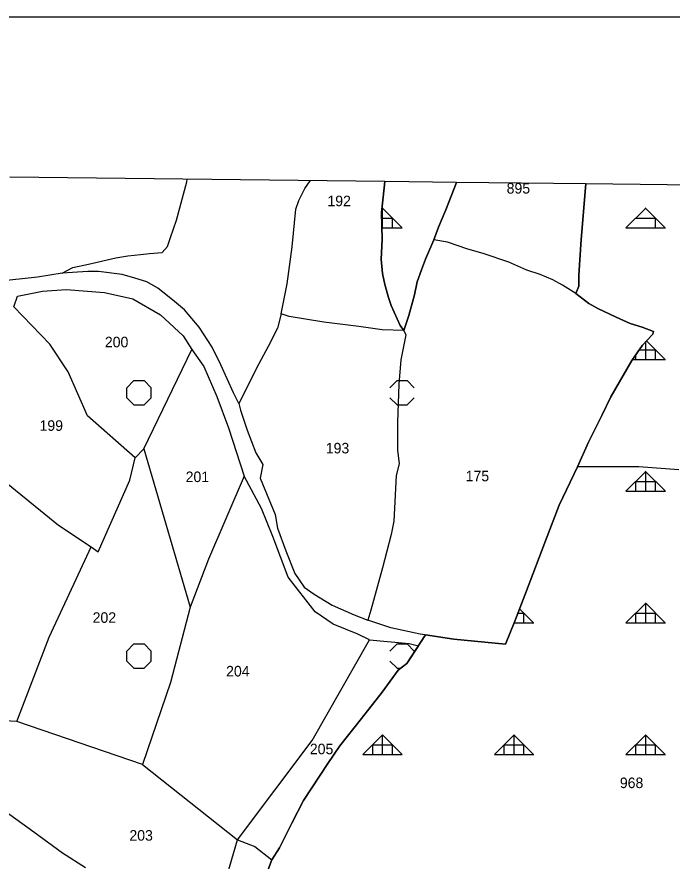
# Model space of a CAD drawing. Extents: x 410727 to 412947, y 4463506 to 4466382.
# Drawn here: x 411696.5 to 411945.5, y 4466061 to 4466381.6 of the extents above; entities that cross this region are included whole.
import ezdxf

# ---------------------------------------------------------------- set-up
doc = ezdxf.new("R2010")
doc.units = 0
for name, color, linetype in [('ADAKENARI', 7, 'Continuous'), ('KDS_PARSEL_NO', 7, 'Continuous'), ('KDS_PL', 7, 'Continuous'), ('LJ_ÇERÇEVE', 7, 'Continuous'), ('PL_AYA_ORMAN', 7, 'Continuous'), ('PL_KA_TARIM_DIGER', 7, 'Continuous'), ('TR_ORMAN', 7, 'Continuous'), ('TR_TARIMALANI', 7, 'Continuous')]:
    doc.layers.add(name, color=color, linetype=linetype)

msp = doc.modelspace()

# ---------------------------------------------------------------- linework, layer by layer
at = {"layer": 'ADAKENARI'}
for p, q in [((411836.11, 4466316.74), (411836.34, 4466319.05)), ((411863.58, 4466318.73), (411859.48, 4466308.27)), ((411910.98, 4466297.07), (411912.75, 4466318.15)), ((411835.02, 4466307.3), (411836.11, 4466316.74)), ((411859.48, 4466308.27), (411856.77, 4466301.73)), ((411835.27, 4466297.12), (411835.02, 4466307.3)), ((411856.77, 4466301.73), (411854.89, 4466297)), ((411834.96, 4466289.56), (411835.27, 4466297.12)), ((411854.89, 4466297), (411851.77, 4466289.54)), ((411910.01, 4466283.5), (411910.98, 4466297.07)), ((411835.45, 4466284.11), (411834.96, 4466289.56)), ((411851.77, 4466289.54), (411850.24, 4466285.57)), ((411850.24, 4466285.57), (411848.64, 4466280.97)), ((411836.29, 4466279.99), (411835.45, 4466284.11)), ((411910.08, 4466279.32), (411910.01, 4466283.5)), ((411837.69, 4466275.03), (411836.29, 4466279.99)), ((411848.64, 4466280.97), (411847.53, 4466276.1)), ((411908.89, 4466276.54), (411910.08, 4466279.32)), ((411847.53, 4466276.1), (411845.41, 4466268.2)), ((411913.91, 4466272.73), (411908.89, 4466276.54)), ((411838.72, 4466272), (411837.69, 4466275.03)), ((411917.32, 4466270.92), (411913.91, 4466272.73)), ((411842.17, 4466264.37), (411838.72, 4466272)), ((411924.21, 4466267.58), (411917.32, 4466270.92)), ((411845.41, 4466268.2), (411843.56, 4466262.55)), ((411929.5, 4466265.21), (411924.21, 4466267.58)), ((411843.56, 4466262.55), (411842.17, 4466264.37)), ((411934.17, 4466263.81), (411929.5, 4466265.21)), ((411938.41, 4466262.07), (411934.17, 4466263.81)), ((411934.24, 4466256.99), (411938.14, 4466261.1)), ((411938.14, 4466261.1), (411938.41, 4466262.07)), ((411930.2, 4466251.07), (411934.24, 4466256.99)), ((411922.23, 4466237.35), (411930.2, 4466251.07)), ((411918.81, 4466230.25), (411922.23, 4466237.35)), ((411918.81, 4466230.25), (411922.23, 4466237.35)), ((411913.66, 4466220.15), (411918.81, 4466230.25)), ((411909.55, 4466210.75), (411913.66, 4466220.15)), ((411902.58, 4466196.22), (411909.55, 4466210.75)), ((411897.34, 4466182.66), (411902.58, 4466196.22)), ((411890.21, 4466163.7), (411897.34, 4466182.66)), ((411885.69, 4466152.18), (411890.21, 4466163.7)), ((411882.2, 4466143.43), (411885.69, 4466152.18)), ((411844.66, 4466136.05), (411851.83, 4466146.91)), ((411851.83, 4466146.91), (411862.55, 4466145.33)), ((411862.55, 4466145.33), (411882.2, 4466143.43)), ((411841.32, 4466133.5), (411844.66, 4466136.05)), ((411835.34, 4466125.15), (411841.32, 4466133.5)), ((411827.4, 4466115.22), (411835.34, 4466125.15)), ((411819.16, 4466104.81), (411827.4, 4466115.22)), ((411814.65, 4466098.13), (411819.16, 4466104.81)), ((411805.34, 4466084.08), (411814.65, 4466098.13)), ((411801.02, 4466075.44), (411805.34, 4466084.08)), ((411796.32, 4466066.11), (411801.02, 4466075.44)), ((411793.41, 4466061.46), (411796.32, 4466066.11)), ((411790.89, 4466054.84), (411793.41, 4466061.46))]:
    msp.add_line(p, q, dxfattribs=at)
at = {"layer": 'KDS_PL'}
for p, q in [((411757.11, 4466304.43), (411761.05, 4466318.91)), ((411761.05, 4466318.91), (411761.24, 4466319.93)), ((411805.93, 4466316.38), (411807.93, 4466319.38)), ((411836.34, 4466319.05), (411836.11, 4466316.74)), ((411859.48, 4466308.27), (411863.58, 4466318.73)), ((411912.75, 4466318.15), (411910.98, 4466297.07)), ((411803.57, 4466311.84), (411805.93, 4466316.38)), ((411836.11, 4466316.74), (411835.02, 4466307.3)), ((411802.54, 4466308.57), (411803.57, 4466311.84)), ((411801.03, 4466294.34), (411802.54, 4466308.57)), ((411856.77, 4466301.73), (411859.48, 4466308.27)), ((411754.87, 4466297.83), (411757.11, 4466304.43)), ((411835.02, 4466307.3), (411835.27, 4466297.12)), ((411854.89, 4466297), (411856.77, 4466301.73)), ((411753.66, 4466294.43), (411754.87, 4466297.83)), ((411835.27, 4466297.12), (411834.96, 4466289.56)), ((411854.89, 4466297), (411851.77, 4466289.54)), ((411860.18, 4466296.1), (411854.89, 4466297)), ((411867.9, 4466293.38), (411860.18, 4466296.1)), ((411910.98, 4466297.07), (411910.01, 4466283.5)), ((411743.42, 4466291.4), (411746.81, 4466291.71)), ((411746.81, 4466291.71), (411751.72, 4466292.07)), ((411751.72, 4466292.07), (411753.66, 4466294.43)), ((411799.21, 4466280.17), (411801.03, 4466294.34)), ((411873.68, 4466291.71), (411867.9, 4466293.38)), ((411883.42, 4466288.44), (411873.68, 4466291.71)), ((411723.67, 4466287.71), (411734.09, 4466290.13)), ((411734.09, 4466290.13), (411738.63, 4466290.86)), ((411738.63, 4466290.86), (411743.42, 4466291.4)), ((411834.96, 4466289.56), (411835.45, 4466284.11)), ((411851.77, 4466289.54), (411850.24, 4466285.57)), ((411890.31, 4466285.45), (411883.42, 4466288.44)), ((411713.62, 4466284.32), (411717.68, 4466286.38)), ((411717.68, 4466286.38), (411723.67, 4466287.71)), ((411850.24, 4466285.57), (411848.64, 4466280.97)), ((411895.39, 4466283.78), (411890.31, 4466285.45)), ((411704.34, 4466282.8), (411688.82, 4466281.1)), ((411713.62, 4466284.32), (411704.34, 4466282.8)), ((411723.46, 4466284.93), (411713.62, 4466284.32)), ((411727.46, 4466284.87), (411723.46, 4466284.93)), ((411736.54, 4466283.84), (411727.46, 4466284.87)), ((411741.33, 4466282.33), (411736.54, 4466283.84)), ((411745.87, 4466280.94), (411741.33, 4466282.33)), ((411835.45, 4466284.11), (411836.29, 4466279.99)), ((411900.19, 4466281.69), (411895.39, 4466283.78)), ((411910.01, 4466283.5), (411910.08, 4466279.32)), ((411749.99, 4466278.57), (411745.87, 4466280.94)), ((411796.94, 4466268.79), (411799.21, 4466280.17)), ((411836.29, 4466279.99), (411837.69, 4466275.03)), ((411848.64, 4466280.97), (411847.53, 4466276.1)), ((411903.88, 4466279.67), (411900.19, 4466281.69)), ((411908.89, 4466276.54), (411903.88, 4466279.67)), ((411910.08, 4466279.32), (411908.89, 4466276.54)), ((411695.25, 4466271.47), (411696.66, 4466275.56)), ((411696.66, 4466275.56), (411706.25, 4466277.44)), ((411706.25, 4466277.44), (411715.19, 4466278.06)), ((411715.19, 4466278.06), (411729.78, 4466276.88)), ((411729.78, 4466276.88), (411740.5, 4466274.59)), ((411755.56, 4466274.15), (411749.99, 4466278.57)), ((411847.53, 4466276.1), (411845.41, 4466268.2)), ((411913.91, 4466272.73), (411908.89, 4466276.54)), ((411740.5, 4466274.59), (411751.06, 4466268.47)), ((411760.11, 4466270.34), (411755.56, 4466274.15)), ((411837.69, 4466275.03), (411838.72, 4466272)), ((411917.32, 4466270.92), (411913.91, 4466272.73)), ((411695.25, 4466271.47), (411709.03, 4466257.31)), ((411765.74, 4466263.73), (411760.11, 4466270.34)), ((411838.72, 4466272), (411842.17, 4466264.37)), ((411924.21, 4466267.58), (411917.32, 4466270.92)), ((411751.06, 4466268.47), (411759.69, 4466260.53)), ((411796.94, 4466268.79), (411795.51, 4466263.34)), ((411799.97, 4466267.88), (411796.94, 4466268.79)), ((411813.11, 4466265.7), (411799.97, 4466267.88)), ((411845.41, 4466268.2), (411843.56, 4466262.55)), ((411929.5, 4466265.21), (411924.21, 4466267.58)), ((411770.65, 4466256.16), (411765.74, 4466263.73)), ((411795.51, 4466263.34), (411791.99, 4466256.43)), ((411826.49, 4466264.07), (411813.11, 4466265.7)), ((411835.33, 4466262.74), (411826.49, 4466264.07)), ((411843.56, 4466262.55), (411835.33, 4466262.74)), ((411842.17, 4466264.37), (411843.56, 4466262.55)), ((411934.17, 4466263.81), (411929.5, 4466265.21)), ((411938.41, 4466262.07), (411934.17, 4466263.81)), ((411759.69, 4466260.53), (411763, 4466255.34)), ((411844.29, 4466260.9), (411842.34, 4466251.36)), ((411843.56, 4466262.55), (411844.29, 4466260.9)), ((411934.24, 4466256.99), (411938.14, 4466261.1)), ((411938.14, 4466261.1), (411938.41, 4466262.07)), ((411715.94, 4466246.88), (411709.03, 4466257.31)), ((411791.99, 4466256.43), (411788.48, 4466249.89)), ((411930.2, 4466251.07), (411934.24, 4466256.99)), ((411744.75, 4466217.53), (411763, 4466255.34)), ((411763, 4466255.34), (411767.53, 4466248.81)), ((411773.95, 4466249.52), (411770.65, 4466256.16)), ((411788.48, 4466249.89), (411780.85, 4466234.74)), ((411842.34, 4466251.36), (411841.65, 4466242.1)), ((411922.23, 4466237.35), (411930.2, 4466251.07)), ((411723.28, 4466230.09), (411715.94, 4466246.88)), ((411767.53, 4466248.81), (411772.5, 4466237.5)), ((411778.79, 4466238.86), (411773.95, 4466249.52)), ((411841.65, 4466242.1), (411841.09, 4466227.55)), ((411772.5, 4466237.5), (411776.84, 4466225.59)), ((411780.85, 4466234.74), (411778.79, 4466238.86)), ((411918.81, 4466230.25), (411922.23, 4466237.35)), ((411780.85, 4466234.74), (411781.44, 4466232.22)), ((411781.44, 4466232.22), (411783.95, 4466224.62)), ((411741.47, 4466214.16), (411723.28, 4466230.09)), ((411841.09, 4466227.55), (411841.16, 4466217.03)), ((411913.66, 4466220.15), (411918.81, 4466230.25)), ((411776.84, 4466225.59), (411782.84, 4466207.25)), ((411783.95, 4466224.62), (411787.23, 4466216.04)), ((411909.55, 4466210.75), (411913.66, 4466220.15)), ((411741.47, 4466214.16), (411744.75, 4466217.53)), ((411744.75, 4466217.53), (411762.28, 4466157.44)), ((411787.23, 4466216.04), (411789.88, 4466211.57)), ((411841.16, 4466217.03), (411841.72, 4466211.88)), ((411739.38, 4466205.62), (411741.47, 4466214.16)), ((411789.88, 4466211.57), (411788.99, 4466206.43)), ((411841.72, 4466211.88), (411840.57, 4466207.45)), ((411687.5, 4466208.69), (411712.31, 4466188.59)), ((411909.55, 4466210.75), (411902.58, 4466196.22)), ((411932.84, 4466210.69), (411909.55, 4466210.75)), ((411948.06, 4466209.59), (411932.84, 4466210.69)), ((411727.38, 4466178.53), (411739.38, 4466205.62)), ((411782.84, 4466207.25), (411769.28, 4466175.62)), ((411789.38, 4466194.91), (411782.84, 4466207.25)), ((411788.99, 4466206.43), (411794.64, 4466192.63)), ((411840.57, 4466207.45), (411839.7, 4466190.09)), ((411902.58, 4466196.22), (411897.34, 4466182.66)), ((411793.78, 4466184.28), (411789.38, 4466194.91)), ((411794.64, 4466192.63), (411795.46, 4466187.47)), ((411839.7, 4466190.09), (411838.68, 4466184.99)), ((411712.31, 4466188.59), (411724.64, 4466180.36)), ((411795.46, 4466187.47), (411798.66, 4466178.87)), ((411799.56, 4466168.81), (411793.78, 4466184.28)), ((411838.68, 4466184.99), (411835.48, 4466172.45)), ((411897.34, 4466182.66), (411890.21, 4466163.7)), ((411720.59, 4466171.62), (411724.64, 4466180.36)), ((411724.64, 4466180.36), (411727.38, 4466178.53)), ((411798.66, 4466178.87), (411802.15, 4466170.26)), ((411769.28, 4466175.62), (411762.28, 4466157.44)), ((411708.78, 4466146.06), (411720.59, 4466171.62)), ((411802.15, 4466170.26), (411805.64, 4466165.01)), ((411835.48, 4466172.45), (411830.97, 4466156.26)), ((411809.88, 4466155.72), (411799.56, 4466168.81)), ((411805.64, 4466165.01), (411809.43, 4466162.39)), ((411890.21, 4466163.7), (411885.69, 4466152.18)), ((411809.43, 4466162.39), (411816.27, 4466158.16)), ((411762.28, 4466157.44), (411754.88, 4466128.81)), ((411816.27, 4466158.16), (411824.71, 4466154.51)), ((411816.72, 4466151), (411809.88, 4466155.72)), ((411824.71, 4466154.51), (411829.8, 4466152.47)), ((411830.97, 4466156.26), (411829.8, 4466152.47)), ((411826.09, 4466147.16), (411816.72, 4466151)), ((411838.54, 4466149.56), (411829.8, 4466152.47)), ((411885.69, 4466152.18), (411882.2, 4466143.43)), ((411849.75, 4466147.22), (411838.54, 4466149.56)), ((411862.55, 4466145.33), (411849.75, 4466147.22)), ((411696.47, 4466114.09), (411708.78, 4466146.06)), ((411808.72, 4466106.81), (411830.47, 4466145.09)), ((411830.47, 4466145.09), (411826.09, 4466147.16)), ((411830.47, 4466145.09), (411845.54, 4466143.62)), ((411882.2, 4466143.43), (411862.55, 4466145.33)), ((411849.07, 4466142.73), (411844.66, 4466136.05)), ((411845.54, 4466143.62), (411849.07, 4466142.73)), ((411844.66, 4466136.05), (411841.32, 4466133.5)), ((411841.32, 4466133.5), (411835.34, 4466125.15)), ((411754.88, 4466128.81), (411744.19, 4466097.72)), ((411835.34, 4466125.15), (411827.4, 4466115.22)), ((411827.4, 4466115.22), (411819.16, 4466104.81)), ((411696.47, 4466114.09), (411685.06, 4466114.5)), ((411744.19, 4466097.72), (411696.47, 4466114.09)), ((411780.34, 4466069.06), (411808.72, 4466106.81)), ((411819.16, 4466104.81), (411814.65, 4466098.13)), ((411744.19, 4466097.72), (411780.34, 4466069.06)), ((411814.65, 4466098.13), (411805.34, 4466084.08)), ((411805.34, 4466084.08), (411801.02, 4466075.44)), ((411702.88, 4466072.06), (411689.12, 4466081.85)), ((411801.02, 4466075.44), (411796.32, 4466066.11)), ((411713.85, 4466064.07), (411702.88, 4466072.06)), ((411775.29, 4466051.91), (411780.34, 4466069.06)), ((411780.34, 4466069.06), (411786.94, 4466066.58)), ((411722.52, 4466058.47), (411713.85, 4466064.07)), ((411786.94, 4466066.58), (411793.41, 4466061.46)), ((411796.32, 4466066.11), (411793.41, 4466061.46)), ((411793.41, 4466061.46), (411790.89, 4466054.84))]:
    msp.add_line(p, q, dxfattribs=at)
at = {"layer": 'LJ_ÇERÇEVE'}
msp.add_lwpolyline([(410732.32, 4466381.6), (412946.74, 4466381.6), (412946.74, 4463506.16), (410732.32, 4463506.16)], close=True, dxfattribs=at)
at = {"layer": 'PL_AYA_ORMAN'}
for points in [[(411995.18, 4466317.19), (411912.75, 4466318.15), (411910.98, 4466297.07), (411910.01, 4466283.5), (411910.08, 4466279.32), (411908.89, 4466276.54), (411913.91, 4466272.73), (411917.32, 4466270.92), (411924.21, 4466267.58), (411929.5, 4466265.21), (411934.17, 4466263.81), (411938.41, 4466262.07), (411938.14, 4466261.1), (411934.24, 4466256.99), (411930.2, 4466251.07), (411922.23, 4466237.35), (411918.81, 4466230.25), (411913.66, 4466220.15), (411909.55, 4466210.75), (411902.58, 4466196.22), (411897.34, 4466182.66), (411890.21, 4466163.7), (411885.69, 4466152.18), (411882.2, 4466143.43), (411862.55, 4466145.33), (411851.83, 4466146.91), (411844.66, 4466136.05), (411841.32, 4466133.5), (411835.34, 4466125.15), (411827.4, 4466115.22), (411819.16, 4466104.81), (411814.65, 4466098.13), (411805.34, 4466084.08), (411801.02, 4466075.44), (411796.32, 4466066.11), (411793.41, 4466061.46), (411790.89, 4466054.84)], [(411863.58, 4466318.73), (411836.34, 4466319.05), (411836.11, 4466316.74), (411835.02, 4466307.3), (411835.27, 4466297.12), (411834.96, 4466289.56), (411835.45, 4466284.11), (411836.29, 4466279.99), (411837.69, 4466275.03), (411838.72, 4466272), (411842.17, 4466264.37), (411843.56, 4466262.55), (411845.41, 4466268.2), (411847.53, 4466276.1), (411848.64, 4466280.97), (411850.24, 4466285.57), (411851.77, 4466289.54), (411854.89, 4466297), (411856.77, 4466301.73), (411859.48, 4466308.27), (411863.58, 4466318.73)]]:
    msp.add_lwpolyline(points, dxfattribs=at)
at = {"layer": 'PL_KA_TARIM_DIGER'}
for points in [[(411912.75, 4466318.15), (411863.58, 4466318.73), (411859.48, 4466308.27), (411856.77, 4466301.73), (411854.89, 4466297), (411851.77, 4466289.54), (411850.24, 4466285.57), (411848.64, 4466280.97), (411847.53, 4466276.1), (411845.41, 4466268.2), (411843.56, 4466262.55), (411842.17, 4466264.37), (411838.72, 4466272), (411837.69, 4466275.03), (411836.29, 4466279.99), (411835.45, 4466284.11), (411834.96, 4466289.56), (411835.27, 4466297.12), (411835.02, 4466307.3), (411836.11, 4466316.74), (411836.34, 4466319.05), (411693.82, 4466320.72)], [(411790.89, 4466054.84), (411793.41, 4466061.46), (411796.32, 4466066.11), (411801.02, 4466075.44), (411805.34, 4466084.08), (411814.65, 4466098.13), (411819.16, 4466104.81), (411827.4, 4466115.22), (411835.34, 4466125.15), (411841.32, 4466133.5), (411844.66, 4466136.05), (411851.83, 4466146.91), (411862.55, 4466145.33), (411882.2, 4466143.43), (411885.69, 4466152.18), (411890.21, 4466163.7), (411897.34, 4466182.66), (411902.58, 4466196.22), (411909.55, 4466210.75), (411913.66, 4466220.15), (411918.81, 4466230.25), (411922.23, 4466237.35), (411930.2, 4466251.07), (411934.24, 4466256.99), (411938.14, 4466261.1), (411938.41, 4466262.07), (411934.17, 4466263.81), (411929.5, 4466265.21), (411924.21, 4466267.58), (411917.32, 4466270.92), (411913.91, 4466272.73), (411908.89, 4466276.54), (411910.08, 4466279.32), (411910.01, 4466283.5), (411910.98, 4466297.07), (411912.75, 4466318.15)]]:
    msp.add_lwpolyline(points, dxfattribs=at)
at = {"layer": 'TR_ORMAN'}
for p, q in [((411835.18, 4466308.66), (411835.45, 4466308.93)), ((411842.75, 4466301.61), (411835.25, 4466309.11)), ((411835.45, 4466301.47), (411835.45, 4466308.97)), ((411927.95, 4466301.44), (411935.45, 4466308.94)), ((411942.74, 4466301.61), (411935.24, 4466309.11)), ((411835.07, 4466305.22), (411839.2, 4466305.22)), ((411839.2, 4466301.47), (411839.2, 4466305.22)), ((411931.7, 4466305.22), (411939.2, 4466305.22)), ((411939.2, 4466301.47), (411939.2, 4466305.22)), ((411835.16, 4466301.47), (411842.95, 4466301.47)), ((411927.95, 4466301.47), (411942.95, 4466301.47)), ((411935.45, 4466251.47), (411935.45, 4466258.27)), ((411942.77, 4466251.59), (411935.76, 4466258.6)), ((411931.7, 4466251.47), (411931.7, 4466253.27)), ((411933.03, 4466255.22), (411939.2, 4466255.22)), ((411939.2, 4466251.47), (411939.2, 4466255.22)), ((411930.47, 4466251.47), (411942.95, 4466251.47)), ((411927.95, 4466201.46), (411935.45, 4466208.96)), ((411942.8, 4466201.57), (411935.3, 4466209.06)), ((411935.45, 4466201.47), (411935.45, 4466208.97)), ((411931.7, 4466201.47), (411931.7, 4466205.22)), ((411931.7, 4466205.22), (411939.2, 4466205.22)), ((411939.2, 4466201.47), (411939.2, 4466205.22)), ((411927.95, 4466201.47), (411942.95, 4466201.47)), ((411892.84, 4466151.54), (411887.52, 4466156.86)), ((411927.95, 4466151.47), (411935.45, 4466158.97)), ((411942.83, 4466151.54), (411935.33, 4466159.04)), ((411935.45, 4466151.47), (411935.45, 4466158.97)), ((411886.88, 4466155.22), (411889.2, 4466155.22)), ((411889.2, 4466151.47), (411889.2, 4466155.22)), ((411931.7, 4466155.22), (411939.2, 4466155.22)), ((411931.7, 4466151.47), (411931.7, 4466155.22)), ((411939.2, 4466151.47), (411939.2, 4466155.22)), ((411885.41, 4466151.47), (411892.95, 4466151.47)), ((411885.45, 4466151.47), (411885.45, 4466151.57)), ((411927.95, 4466151.47), (411942.95, 4466151.47)), ((411827.95, 4466101.46), (411835.45, 4466108.96)), ((411842.88, 4466101.52), (411835.38, 4466109.02)), ((411835.45, 4466101.47), (411835.45, 4466108.97)), ((411877.95, 4466101.47), (411885.45, 4466108.97)), ((411892.87, 4466101.52), (411885.37, 4466109.02)), ((411885.45, 4466101.47), (411885.45, 4466108.97)), ((411927.95, 4466101.47), (411935.45, 4466108.97)), ((411942.86, 4466101.52), (411935.37, 4466109.02)), ((411935.45, 4466101.47), (411935.45, 4466108.97)), ((411831.7, 4466101.47), (411831.7, 4466105.22)), ((411831.7, 4466105.22), (411839.2, 4466105.22)), ((411839.2, 4466101.47), (411839.2, 4466105.22)), ((411881.7, 4466105.22), (411889.2, 4466105.22)), ((411881.7, 4466101.47), (411881.7, 4466105.22)), ((411889.2, 4466101.47), (411889.2, 4466105.22)), ((411931.7, 4466101.47), (411931.7, 4466105.22)), ((411931.7, 4466105.22), (411939.2, 4466105.22)), ((411939.2, 4466101.47), (411939.2, 4466105.22)), ((411827.95, 4466101.47), (411842.95, 4466101.47)), ((411877.95, 4466101.47), (411892.95, 4466101.47)), ((411927.95, 4466101.47), (411942.95, 4466101.47))]:
    msp.add_line(p, q, dxfattribs=at)
at = {"layer": 'TR_TARIMALANI'}
for p, q in [((411738.25, 4466240.8), (411740.96, 4466243.5)), ((411740.96, 4466243.51), (411744.79, 4466243.51)), ((411747.5, 4466240.8), (411744.79, 4466243.5)), ((411838.25, 4466240.8), (411840.95, 4466243.5)), ((411840.96, 4466243.51), (411844.79, 4466243.51)), ((411847.5, 4466240.8), (411844.79, 4466243.5)), ((411738.25, 4466236.97), (411738.25, 4466240.8)), ((411747.5, 4466236.97), (411747.5, 4466240.8)), ((411740.96, 4466234.26), (411738.25, 4466236.96)), ((411744.79, 4466234.26), (411747.5, 4466236.96)), ((411840.96, 4466234.26), (411838.25, 4466236.96)), ((411844.79, 4466234.26), (411847.49, 4466236.96)), ((411740.96, 4466234.26), (411744.79, 4466234.26)), ((411840.96, 4466234.26), (411844.79, 4466234.26)), ((411738.25, 4466140.8), (411740.96, 4466143.5)), ((411738.25, 4466136.97), (411738.25, 4466140.8)), ((411740.96, 4466143.51), (411744.79, 4466143.51)), ((411747.5, 4466140.8), (411744.79, 4466143.5)), ((411747.5, 4466136.97), (411747.5, 4466140.8)), ((411838.25, 4466140.8), (411840.95, 4466143.5)), ((411840.96, 4466143.51), (411844.79, 4466143.51)), ((411847.5, 4466140.8), (411844.79, 4466143.5)), ((411740.96, 4466134.26), (411738.25, 4466136.96)), ((411744.79, 4466134.26), (411747.5, 4466136.96)), ((411840.96, 4466134.26), (411838.25, 4466136.96)), ((411740.96, 4466134.26), (411744.79, 4466134.26)), ((411840.96, 4466134.26), (411842.32, 4466134.26))]:
    msp.add_line(p, q, dxfattribs=at)

# ---------------------------------------------------------------- texts
at = {"layer": 'KDS_PARSEL_NO'}
for s, p in [('895', (411882.61, 4466314.51)), ('192', (411814.48, 4466309.7)), ('200', (411729.9, 4466256.13)), ('199', (411705.07, 4466224.42)), ('193', (411813.86, 4466215.85)), ('201', (411760.61, 4466204.96)), ('175', (411867.03, 4466205.26)), ('202', (411725.25, 4466151.51)), ('204', (411775.98, 4466131.15)), ('205', (411807.81, 4466101.6)), ('968', (411925.64, 4466088.75)), ('203', (411739.22, 4466068.79))]:
    msp.add_text(s, height=4, dxfattribs=at).set_placement(p)

doc.saveas('drawing.dxf')
